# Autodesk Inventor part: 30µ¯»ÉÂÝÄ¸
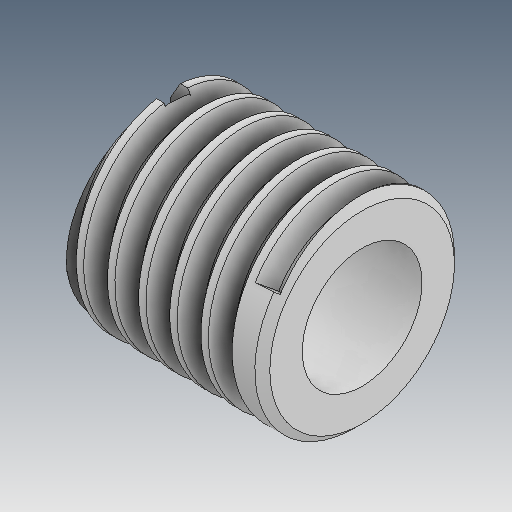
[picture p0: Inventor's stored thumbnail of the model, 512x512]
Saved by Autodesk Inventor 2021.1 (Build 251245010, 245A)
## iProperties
Created: 2019-12
Part Number: 30µ¯»ÉÂÝÄ¸
Material: Ogólny
Document SubType Name: Modeling
Designer: user
Density: 1 g/cm^3
Appearance: Domyślna
Author: user
Revision Number: ÈÎºÎ
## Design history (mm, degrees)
feature "ÊäÈë1"
node "Bryła1"
